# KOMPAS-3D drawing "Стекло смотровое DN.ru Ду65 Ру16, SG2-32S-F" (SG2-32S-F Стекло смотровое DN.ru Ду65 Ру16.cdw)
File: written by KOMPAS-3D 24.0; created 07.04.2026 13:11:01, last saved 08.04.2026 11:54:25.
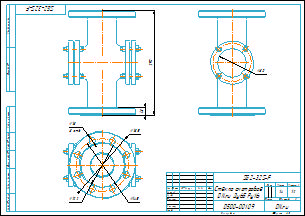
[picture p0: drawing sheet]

Document properties: Автор: Main; Форматы листов документа: A3; Полное имя файла: SG2-32S-F Стекло смотровое DN.ru Ду65 Ру16.m3d; Масса: 14; Наименование: Стекло смотровое DN.ru Ду65 Ру16; Количество листов документа: 1; Примечание: D500-00109

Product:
- Body: Тело 1  | qty 1
    Масса: 13.01185
- Part/product: Стекло смотровое DN.ru Ду65 Ру16  | designation SG2-32S-F
    Масса: 14
    Раздел спецификации: Прочие изделия
    Примечание: D500-00109

Views: Вид 1, Снизу, Проекционный вид 2
Referenced files in D:\DN.ru Аутсерс\Стекло смотровое DN.ru\Стекло смотровое DN.ru SG2-34G-F тип В ГОСТ 21836-2021 Ду100 Ру16, углеродистая сталь, фланцевое\: SG2-34G-F тип В Стекло смотровое DN.ru Ду100 Ру16.m3d, SG2-34G-F тип ВСтекло смотровое DN.ru Ду100 Ру16.cdw
Referenced files in D:\DN.ru Аутсерс\Стекло смотровое DN.ru\SG2-32S-F Стекло смотровое DN.ru Ду65 Ру16\: SG2-32S-F Стекло смотровое DN.ru Ду65 Ру16.m3d
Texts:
  SG2-32S-F
  Стекло смотровое
  DN.ru Ду65 Ру16
  Стекло смотровое DN.ru Ду65 Ру16
  SG2-32S-F Стекло смотровое DN.ru Ду65 Ру16
Dimensions and other numbers on the sheet: 0; 3; 2; 4; 290; 18; 8 отв.; 185; 145; 122; 1:2; 1; 14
